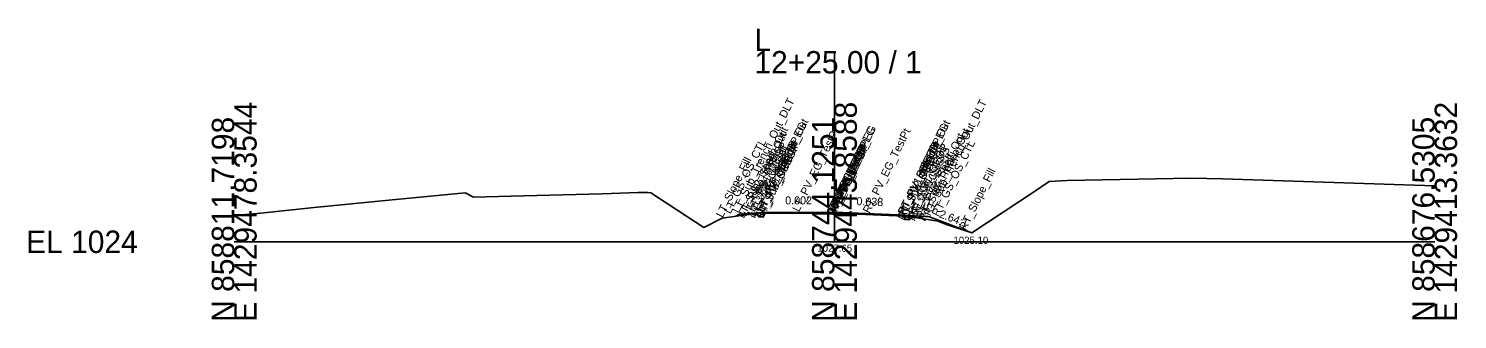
# Model space of a CAD drawing. Extents: x -26 to 153, y -10 to 13058.
# Drawn here: x -25.7 to 152.8, y 1490.3 to 1526.6 of the extents above; entities that cross this region are included whole.
import ezdxf

# ---------------------------------------------------------------- set-up
doc = ezdxf.new("R2010")
doc.units = 0
for name, color, linetype in [('Default', 7, 'Continuous'), ('Exist Cross Section Cell', 7, 'Continuous'), ('Exist XS Center Line Elevation Label', 7, 'Continuous'), ('Exist XS Ground Line', 7, 'Continuous'), ('Prop CMT Pvmt Course 1', 7, 'Continuous'), ('Prop CMT Pvmt Surface', 7, 'Continuous'), ('Prop CMT Pvmt Surface Shoulder', 7, 'Continuous'), ('Prop CMT Pvmt Wedge Surface 1', 7, 'Continuous'), ('Prop CMT Shld Paved Course 1', 7, 'Continuous'), ('Prop CMT Slope Grass', 7, 'Continuous'), ('Prop CMT Subgrade Earthwork', 7, 'Continuous'), ('Prop XS Dump Level', 7, 'Continuous'), ('Prop XS SE Text', 7, 'Continuous'), ('Prop XS Side Slope Text', 7, 'Continuous')]:
    doc.layers.add(name, color=color, linetype=linetype)

msp = doc.modelspace()

# ---------------------------------------------------------------- linework, layer by layer
at = {"layer": 'Exist Cross Section Cell'}
for p, q in [((75, 1500), (75, 1523.82)), ((0, 1500), (75, 1500)), ((75, 1500), (150, 1500))]:
    msp.add_line(p, q, dxfattribs=at)
at = {"layer": 'Exist XS Ground Line'}
msp.add_lwpolyline([(0, 1503.29), (3.32, 1503.57), (9.98, 1504.29), (19.3, 1505.18), (28.85, 1506.1), (29.89, 1505.58), (36.2, 1505.74), (45.97, 1505.99), (50.43, 1506.16), (51.72, 1506.15), (52.07, 1506.13), (58.69, 1501.79), (60.95, 1502.93), (63.06, 1503.23), (66.11, 1503.67), (72.62, 1503.66), (75.1, 1503.65), (81.49, 1503.39), (83.76, 1503.3), (85.55, 1502.96), (87.94, 1502.56), (88.86, 1502.21), (92.16, 1501.1), (99.87, 1506.19), (101.83, 1507.51), (104.08, 1507.64), (119.53, 1507.94), (123.54, 1507.86), (144.94, 1507.17), (150, 1506.99)], dxfattribs=at)
at = {"layer": 'Prop CMT Pvmt Course 1'}
for points in [[(75, 1503.68), (66.13, 1503.67)], [(66.13, 1503.67), (66.13, 1503.12), (66.13, 1503.12), (66.13, 1503.54)], [(66.13, 1503.54), (75, 1503.56)], [(75, 1503.14), (75, 1503.68)], [(75, 1503.68), (83.88, 1503.34)], [(75, 1503.14), (75, 1503.68)], [(75, 1503.56), (75, 1503.14), (75, 1503.14)], [(83.76, 1503.22), (75, 1503.56)], [(75, 1503.56), (75, 1503.14), (75, 1503.14)], [(83.88, 1503.34), (83.88, 1502.8)], [(83.76, 1502.81), (83.76, 1503.22)], [(83.88, 1502.8), (83.76, 1502.81)]]:
    msp.add_lwpolyline(points, dxfattribs=at)
at = {"layer": 'Prop CMT Pvmt Surface'}
for points in [[(75, 1503.68), (66.13, 1503.67)], [(75, 1503.68), (83.88, 1503.34)]]:
    msp.add_lwpolyline(points, dxfattribs=at)
at = {"layer": 'Prop CMT Pvmt Surface Shoulder'}
for points in [[(66.13, 1503.67), (66.13, 1503.67)], [(83.88, 1503.34), (83.88, 1503.34)]]:
    msp.add_lwpolyline(points, dxfattribs=at)
at = {"layer": 'Prop CMT Pvmt Wedge Surface 1'}
for points in [[(66.13, 1503.12), (66.13, 1503.67)], [(75, 1503.56), (66.13, 1503.54)], [(66.13, 1503.54), (66.13, 1503.12), (66.13, 1503.12)], [(75, 1503.56), (83.76, 1503.22)], [(83.88, 1502.8), (83.88, 1503.34)], [(83.76, 1503.22), (83.76, 1502.81)], [(83.76, 1502.81), (83.88, 1502.8)]]:
    msp.add_lwpolyline(points, dxfattribs=at)
at = {"layer": 'Prop CMT Shld Paved Course 1'}
for points in [[(66.13, 1503.67), (65.57, 1503.11)], [(66.13, 1503.67), (66.13, 1503.67)], [(66.13, 1503.12), (66.13, 1503.67)], [(83.88, 1503.34), (83.88, 1503.34)], [(83.88, 1503.34), (84.43, 1502.79)], [(83.88, 1502.8), (83.88, 1503.34)], [(65.57, 1503.11), (66.13, 1503.12)], [(84.43, 1502.79), (83.88, 1502.8)]]:
    msp.add_lwpolyline(points, dxfattribs=at)
at = {"layer": 'Prop CMT Slope Grass'}
for points in [[(66.13, 1503.67), (63.13, 1503.43), (62.6, 1503.16)], [(83.88, 1503.34), (86.88, 1503.1), (92.16, 1501.1)]]:
    msp.add_lwpolyline(points, dxfattribs=at)
at = {"layer": 'Prop CMT Subgrade Earthwork'}
for points in [[(65.57, 1503.11), (65.1, 1503.58)], [(66.13, 1503.12), (66.14, 1503.67)], [(83.76, 1502.81), (83.75, 1503.3)], [(84.43, 1502.79), (84.9, 1503.26)], [(66.13, 1503.12), (65.57, 1503.11)], [(66.13, 1503.12), (66.13, 1503.12)], [(83.76, 1502.81), (83.88, 1502.8)], [(83.88, 1502.8), (84.43, 1502.79)]]:
    msp.add_lwpolyline(points, dxfattribs=at)

# ---------------------------------------------------------------- texts
at = {"layer": 'Default'}
for s, height, p in [('-', 0.0001, (0, 1500)), ('1025.10', 0.9, (89.87, 1499.74))]:
    msp.add_text(s, height=height, dxfattribs=at).set_placement(p)
at = {"layer": 'Exist Cross Section Cell'}
for s, p in [('L', (65, 1523.82)), ('12+25.00 / 1', (65, 1521.02)), ('EL 1024', (-26, 1498.6))]:
    msp.add_text(s, height=2.8, dxfattribs=at).set_placement(p)
for s, p in [('E 1429478.3544', (2.8, 1490)), ('E 1429445.8588', (77.8, 1490)), ('E 1429413.3632', (152.8, 1490)), ('N 858811.7198', (0, 1490)), ('N 858744.1251', (75, 1490)), ('N 858676.5305', (150, 1490))]:
    msp.add_text(s, height=2.8, rotation=90, dxfattribs=at).set_placement(p)
at = {"layer": 'Exist XS Center Line Elevation Label'}
msp.add_text('1027.65', height=0.9, dxfattribs=at).set_placement((72.86, 1498.75))
msp.add_text('1027.65', height=0.9, dxfattribs=at).set_placement((72.86, 1498.75))
msp.add_text('1027.65', height=0.9, dxfattribs=at).set_placement((72.86, 1498.75))
at = {"layer": 'Prop XS Dump Level'}
for s, p in [('LT_Sub_Trench_Out_DLT', (63.03, 1503.51)), ('RT_Sub_Trench_Out_DLT', (86.97, 1503.14)), ('LT_Sub_Trench_Out', (63.69, 1502.85)), ('LT_PV_OEEOP_EG', (66.11, 1503.67)), ('LT_PV_Sub_Tie_Out', (66.13, 1503.67)), ('LT_PV_EG_TestPt', (70.56, 1503.66)), ('RT_PV_IEEOP_EG', (75, 1503.65)), ('LT_PV_IEEOP_EG', (75, 1503.65)), ('RT_PV_EG_TestPt', (79.38, 1503.47)), ('RT_PV_Sub_Tie_Out', (83.75, 1503.3)), ('RT_PV_OEEOP_EG', (83.76, 1503.3)), ('RT_Sub_Trench_Out', (86.31, 1502.48)), ('LT_GS_OS_CTL', (62, 1503.42)), ('LT_PS2_Shelf_Out', (63.95, 1503.1)), ('LT_PV1_OEOT', (65, 1503.66)), ('LT_PS1_OEOP', (65, 1503.66)), ('LT_PV1_OEEOP', (66.11, 1503.54)), ('LT_PV2_OEEOP', (66.11, 1503.12)), ('LT_Sub_OEEOP', (66.11, 1502.87)), ('RT_PV1_IEEOP', (75, 1503.56)), ('LT_PV1_IEEOP', (75, 1503.56)), ('RT_PV2_IEEOP', (75, 1503.14)), ('RT_PV1_OEEOP', (83.76, 1503.22)), ('RT_PV2_OEEOP', (83.76, 1502.81)), ('RT_Sub_OEEOP', (83.76, 1502.56)), ('RT_PV1_OEOT', (85, 1503.3)), ('RT_PS1_OEOP', (85, 1503.3)), ('RT_PS2_Shelf_Out', (86.05, 1502.74)), ('RT_GS_OS_CTL', (88, 1503.06)), ('LT_Slope_Fill', (61.03, 1502.94)), ('LT_PS2_OEOP', (64.45, 1503.11)), ('LT_PV2_OEOT', (65, 1503.12)), ('LT_Sub_OEOT', (65, 1502.87)), ('LT_PV2_IEEOP', (75, 1503.14)), ('RT_PV2_OEOT', (85, 1502.76)), ('RT_Sub_OEOT', (85, 1502.51)), ('RT_PS2_OEOP', (85.55, 1502.75)), ('PV1_PGL', (75, 1503.68)), ('RT_Slope_Fill', (91.42, 1501.35)), ('PV2_PGL', (75, 1503.14))]:
    msp.add_text(s, height=1, rotation=63.5833, dxfattribs=at).set_placement(p)
at = {"layer": 'Prop XS SE Text'}
for s, rotation, p in [('0.002', 0.0917, (68.85, 1504.67)), ('0.038', 357.8238, (77.73, 1504.58))]:
    msp.add_text(s, height=1, rotation=rotation, dxfattribs=at).set_placement(p)
at = {"layer": 'Prop XS Side Slope Text'}
msp.add_text('2.64:1', height=1, rotation=339.2636, dxfattribs=at).set_placement((88.01, 1503.08))

doc.saveas('drawing.dxf')
